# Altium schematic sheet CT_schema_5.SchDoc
size 368 x 245 mm
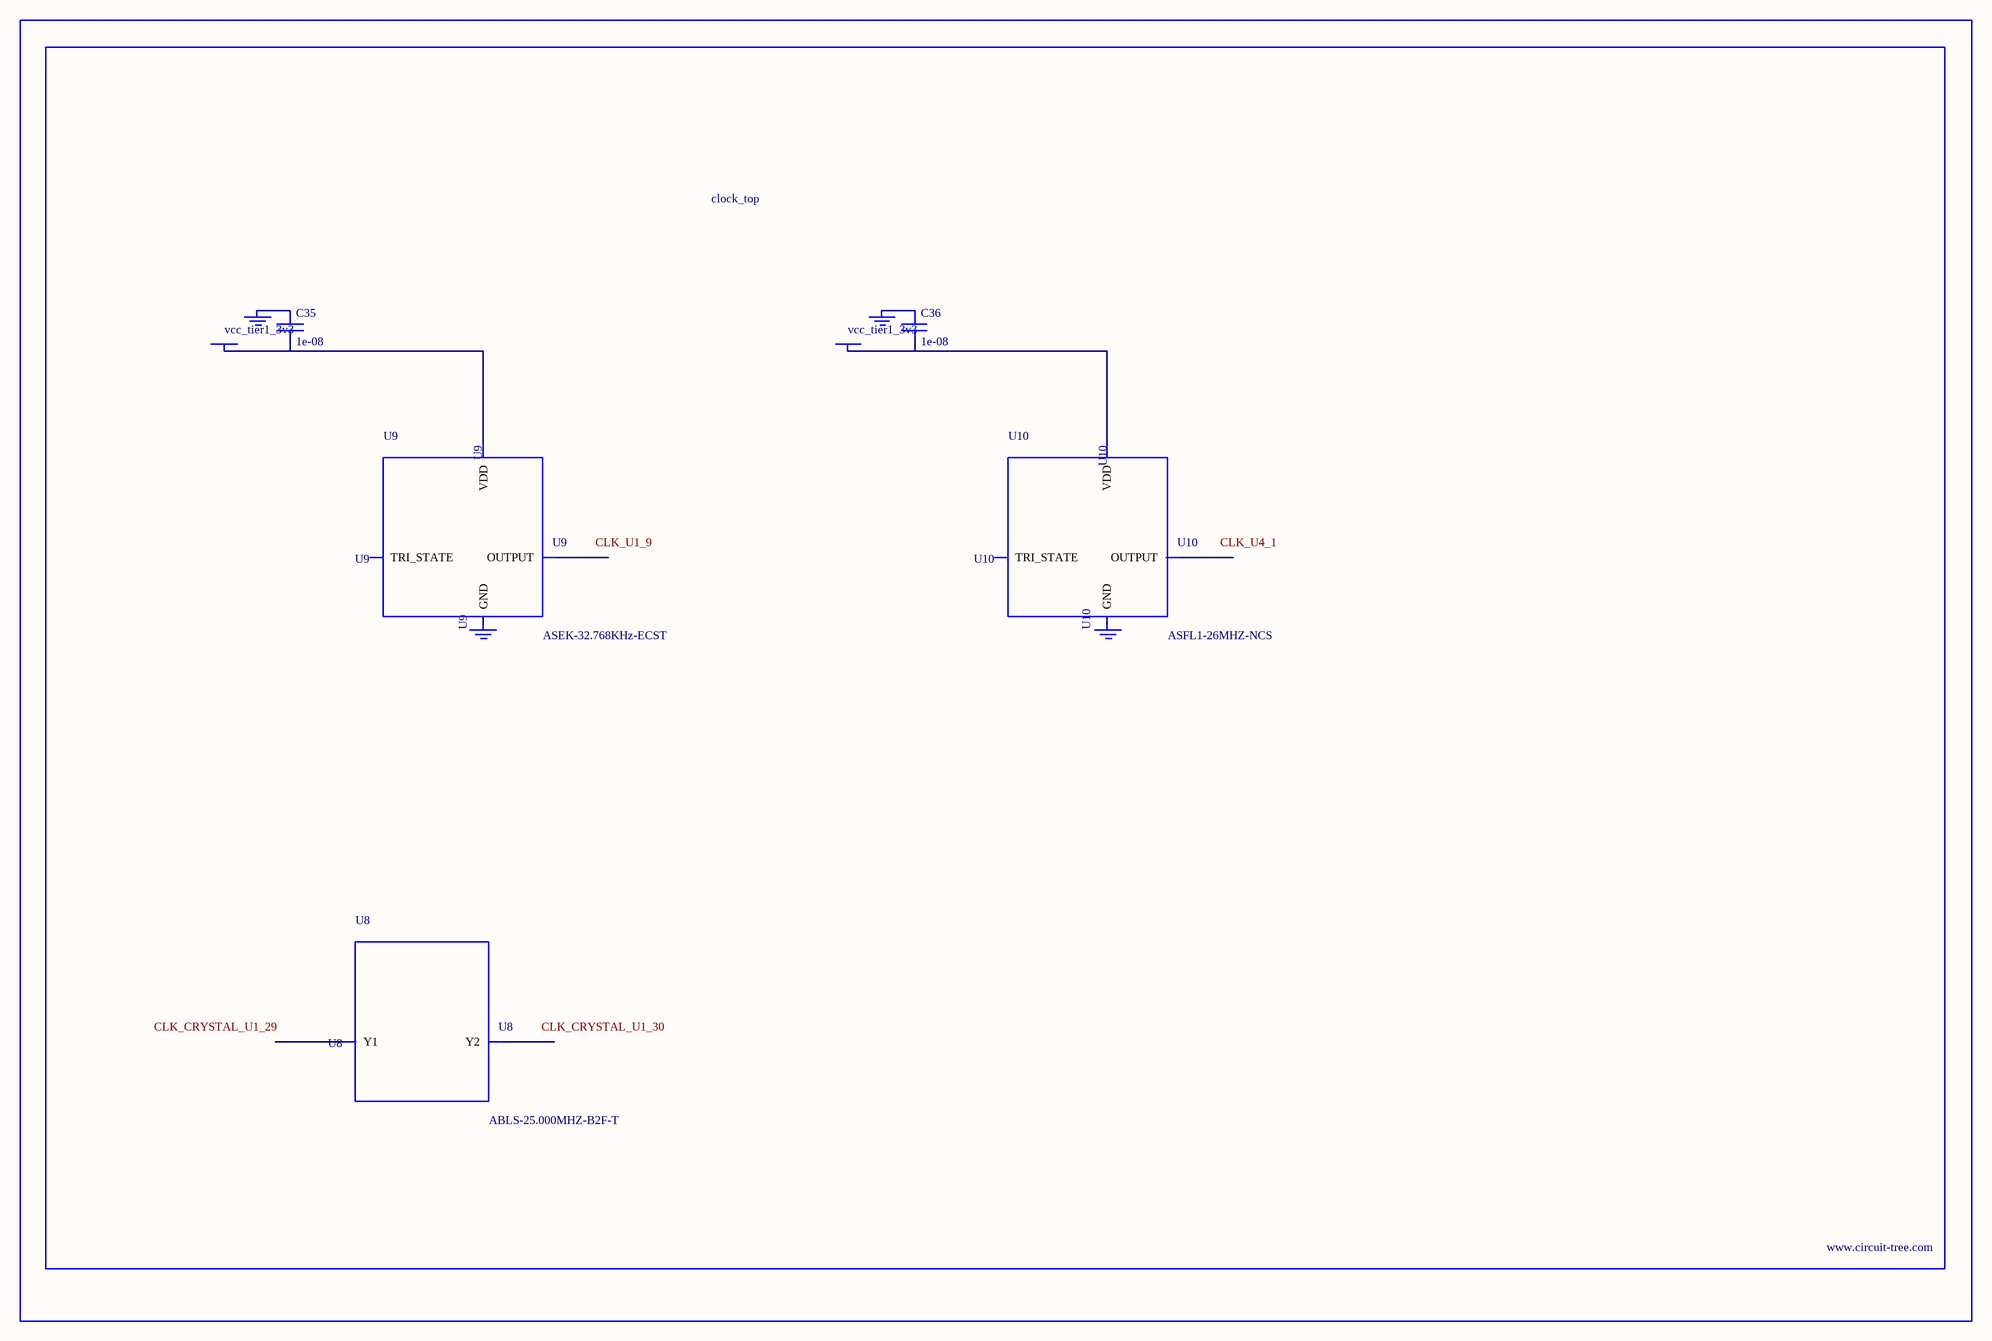
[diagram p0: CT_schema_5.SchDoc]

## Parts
BORDER4  (no value)
C35  1e-08  [C0402]
C36  1e-08  [C0402]
GND_INSTANCE_4_0  (no value)
GND_INSTANCE_4_1  (no value)
GND_INSTANCE_4_2  (no value)
GND_INSTANCE_4_3  (no value)
POWER_INSTANCE_4_0  vcc_tier1_3v3
POWER_INSTANCE_4_1  vcc_tier1_3v3
U8  ABLS-25.000MHZ-B2F-T  [ABLS-25.000MHZ-B2F-T]
U9  ASEK-32.768KHz-ECST  [ASEK]
U10  ASFL1-26MHZ-NCS  [ASFL1]

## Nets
NetC35_1: C35.1 GND_INSTANCE_4_0.0(GND)
NetC35_2: C35.2 POWER_INSTANCE_4_0.0(PWR) U9.4(VDD)
NetC36_1: C36.1 GND_INSTANCE_4_2.0(GND)
NetC36_2: C36.2 POWER_INSTANCE_4_1.0(PWR) U10.4(VDD)

Not connected (* = marked no-connect by the designer): GND_INSTANCE_4_1 0(GND); GND_INSTANCE_4_3 0(GND); U8 1(Y1) 2(Y2); U9 1(TRI_STATE) 2(GND) 3(OUTPUT); U10 1(TRI_STATE) 2(GND) 3(OUTPUT)

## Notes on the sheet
- Labels drawn without touching a wire or pin: CLK_CRYSTAL_U1_29, CLK_CRYSTAL_U1_30, CLK_U1_9, CLK_U4_1

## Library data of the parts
BORDER4 = BORDER_PAGE4
C35 C36 = C0402C103K3RAC
GND_INSTANCE_4_0-GND_INSTANCE_4_3 = GND
POWER_INSTANCE_4_0 POWER_INSTANCE_4_1 = PWR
